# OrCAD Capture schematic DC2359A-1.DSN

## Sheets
1 PAGE2: size A
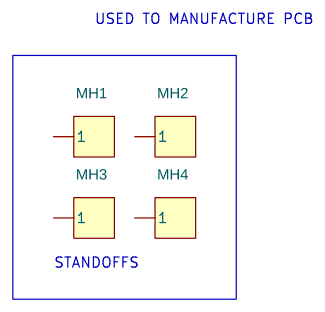
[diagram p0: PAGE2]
2 PAGE1: size Custom; title: MONOLITHIC SYNCHRONOUS BUCK REGULATOR; rev: 1; company: TM; note: WITH ULTRA-LOW QUIESCENT CURRENT
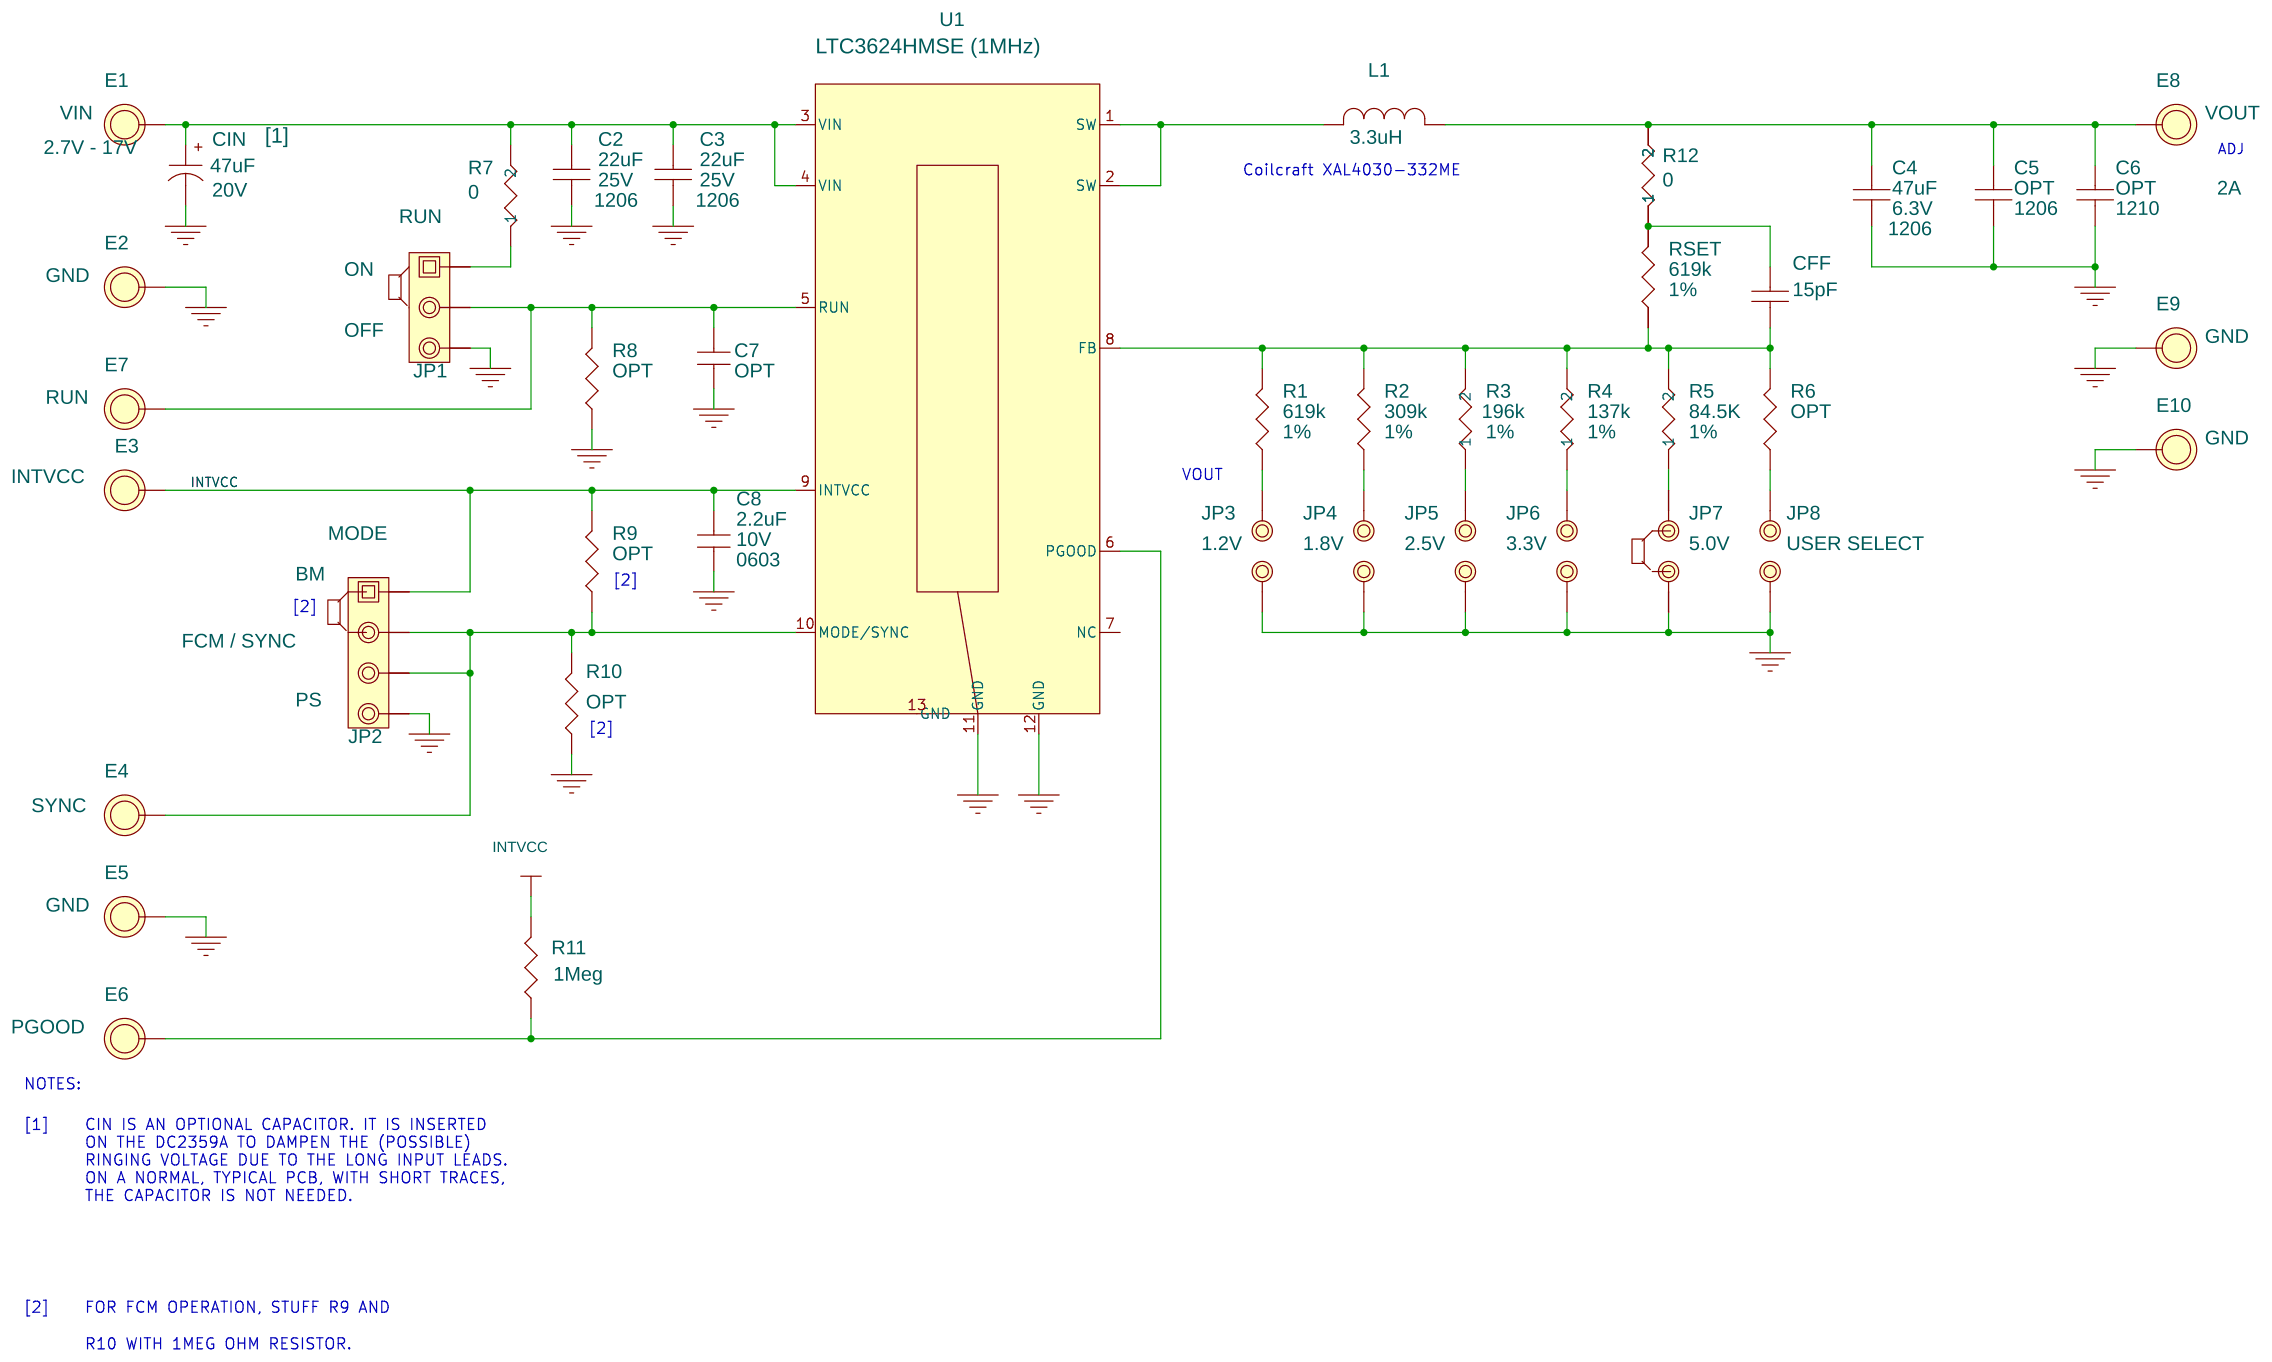
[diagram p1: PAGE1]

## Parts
sheet PAGE1
C2  22uF  [1206]
C3  22uF  [1206]
C4  47uF  [1206]
C5  OPT  [1206]
C6  OPT  [1210]
C7  OPT  [0402]
C8  2.2uF  [0603]
CFF  15pF  [0402]
CIN  47uF  [7343]
E1  2.7V - 17V  [TP\MMX\2501-2]
E2  2.7V - 17V  [TP\MMX\2501-2]
E3  3.6V  [TP\MMX\2501-2]
E4  3A  [TP\MMX\2501-2]
E5  2.7V - 17V  [TP\MMX\2501-2]
E6  3A  [TP\MMX\2501-2]
E7  2.7V - 17V  [TP\MMX\2501-2]
E8  2A  [TP\MMX\2501-2]
E9  2A  [TP\MMX\2501-2]
E10  2A  [TP\MMX\2501-2]
JP1  3 Pins 2mm Ctrs.  [SIP\3P\2MM]
JP2  3 Pins 2mm Ctrs.  [SIP\4P\2MM]
JP3  2 Pins 2mm Ctrs.  [SIP\2P\2MM]
JP4  2 Pins 2mm Ctrs.  [SIP\2P\2MM]
JP5  2 Pins 2mm Ctrs.  [SIP\2P\2MM]
JP6  2 Pins 2mm Ctrs.  [SIP\2P\2MM]
JP7  2 Pins 2mm Ctrs.  [SIP\2P\2MM]
JP8  2 Pins 2mm Ctrs.  [SIP\2P\2MM]
L1  3.3uH  [IND\CLCRF_XAL4020]
R1  619k  [R0402]
R2  309k  [R0402]
R3  196k  [R0402]
R4  137k  [R0402]
R5  84.5K  [R0402]
R6  OPT  [R0402]
R7  0  [R0402]
R8  OPT  [0402]
R9  OPT  [R0402]
R10  OPT  [0402]
R11  1Meg  [0402]
R12  0  [R0402]
RSET  619k  [R0402]
U1  LTC3624HMSE (1MHz)  [LT_MSE_12]
XJP1  2mm Ctrs.
XJP2  2mm Ctrs.
XJP3  2mm Ctrs.
sheet PAGE2
MH1  CON1  [KEYSTONE_8831]
MH2  CON1  [KEYSTONE_8831]
MH3  CON1  [KEYSTONE_8831]
MH4  CON1  [KEYSTONE_8831]

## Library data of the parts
C2 C3 = CAP_NP: CAP, 1206 22uF10% 25V X5R; FIELD1: 0805; Part Number: MURATA GRM31CR61E226KE15L; Tolerance: X5R; Voltage: 25V
C4 = CAP_NP: CAP, 1206 47uF 20% 6.3V X5R; FIELD1: 0805; Part Number: TAIYO YUDEN JMK316BJ476ML-T; Tolerance: X5R; Voltage: 6.3V
C5 = CAP_NP: CAP, 1206 22uF 20% 6.3V X5R OPTION; FIELD1: 0805; Part Number: TAIYO YUDEN EMK316BJ226ML-T OPTION; Tolerance: X5R; Voltage: 6.3V
C6 = CAP_NP_0: CAP, 1210 OPTION; Part Number: OPTION
C7 = CAP0603: CAP, 0402 OPTION; Part Number: OPTION
C8 = CAP0402: CAP, 0603 2.2uF 10% 10V X5R; 1ST PART FIELD: 10V; Part Number: AVX 0603ZDF225KAT2A
CFF = CAP_NP: CAP, 0402 15pF 1% 50V C0G; Case: 1206; Part Number: AVX 04025U150FAT2A; Tolerance: NPO; Voltage: 50V
CIN = CAP+7343: CAP, 47uF 20% 20V 33m Ohm; 1ST PART FIELD: 20V; 2ND PART FIELD: OPT; 4TH PART FIELD: [1]; Part Number: PANASONIC OSCON 20SVPA47M
E1 = E_4: TURRET; INPUT: VIN; Part Number: MILL-MAX 2501-2-00-80-00-00-07-0; STATUS: 1.6V, 1.8V, 2.0V OR 2.5V @ 15A
E2 E5 E9 E10 = E_4: TURRET; INPUT: GND; Part Number: MILL-MAX 2501-2-00-80-00-00-07-0; STATUS: 1.6V, 1.8V, 2.0V OR 2.5V @ 15A
E3 = E_4: TURRET; INPUT: INTVCC; Part Number: MILL-MAX 2501-2-00-80-00-00-07-0; STATUS: 1.6V, 1.8V, 2.0V OR 2.5V @ 15A
E4 = E_4: TURRET; INPUT: SYNC; Part Number: MILL-MAX 2501-2-00-80-00-00-07-0; STATUS: 1.6V, 1.8V, 2.0V OR 2.5V @ 15A
E6 = E_4: TURRET; INPUT: PGOOD; Part Number: MILL-MAX 2501-2-00-80-00-00-07-0; STATUS: 1.6V, 1.8V, 2.0V OR 2.5V @ 15A
E7 = E_4: TURRET; INPUT: RUN; Part Number: MILL-MAX 2501-2-00-80-00-00-07-0; STATUS: 1.6V, 1.8V, 2.0V OR 2.5V @ 15A
E8 = E_4: TURRET; INPUT: VOUT; Part Number: MILL-MAX 2501-2-00-80-00-00-07-0; STATUS: 1.6V, 1.8V, 2.0V OR 2.5V @ 15A
JP1 = Samtec_TMM-103-02-L-S: HEADER, 3PIN, 2mm; 11th Part Field: OFF; 12th Part Field: RUN; 9th Part Field: ON; Part Number: WURTH 620 003 111 21
JP2 = Samtec_TMM-103-02-L-S_0: HEADER, 4PIN, 2mm; 11th Part Field: FCM / SYNC; 12th Part Field: MODE; 4th Part Field: PS; 5th Part Field: ON1_CONTROL; 9th Part Field: BM; Part Number: SAMTEC TMM-104-02-L-S
JP3 = Samtec_TMM-102-02-L-S_4: HEADER, 2PIN, 2mm; 9th Part Field: 1.2V; Part Number: SAMTEC TMM 102-02-L-S
JP4 = Samtec_TMM-102-02-L-S_5: HEADER, 2PIN, 2mm; 9th Part Field: 1.8V; Part Number: SAMTEC TMM 102-02-L-S
JP5 = Samtec_TMM-102-02-L-S_3: HEADER, 2PIN, 2mm; 9th Part Field: 2.5V; Part Number: SAMTEC TMM 102-02-L-S
JP6 = Samtec_TMM-102-02-L-S_2: HEADER, 2PIN, 2mm; 9th Part Field: 3.3V; Part Number: SAMTEC TMM 102-02-L-S
JP7 = Samtec_TMM-102-02-L-S: HEADER, 2PIN, 2mm; 9th Part Field: 5.0V; Part Number: SAMTEC TMM 102-02-L-S
JP8 = Samtec_TMM-102-02-L-S_1: HEADER, 2PIN, 2mm; 9th Part Field: USER SELECT; Part Number: SAMTEC TMM 102-02-L-S
L1 = D53LC: IND, 3.3uH; Part Number: COILCRAFT XAL4030-332ME
R1 RSET = RESISTOR: RES, 0402 619K OHM 1% 1/16W; Part Number: VISHAY CRCW0402619KFKED; Tol: 1%
R2 = RESISTOR: RES, 0402 309k OHMS 1% 1/16W; Part Number: VISHAY CRCW0402309KFKED; Tolerance: 1%
R3 = R_1: RES, 0402 196K OHMS 1% 1/16W; 5%: 1%; Part Number: VISHAY CRCW0402196KFKEA; Tol: 1%
R4 = R: RES, 0402 137K OHMS 1% 1/16W; 5%: 1%; Part Number: VISHAY CRCW0402137KFKED; Tol: 1%
R5 = R_2: RES, 0402 84.5K OHMS 1% 1/16W; 5%: 1%; Part Number: VISHAY CRCW040284K5FKED
R6 = RESISTOR: RES, 0402 OPTION; Part Number: OPTION; Tolerance: 1%
R7 = R_4: RES, 0402 0 OHM JUMPER; 5%: 1%; Part Number: VISHAY CRCW04020000Z0ED
R8 = RESISTOR: RES, 0402 OPTION; Part Number: OPTION
R9 = RESISTOR: RES, 0402 OPTION; Part Number: OPTION; Tol: <Tol>
R10 = AAC-0402: RES, 0402 OPTION; 4TH PART FIELD: AAC,; Part Number: OPTION
R11 = AAC-0402: RES, 0402 1M OHMS 5% 1/16W; 4TH PART FIELD: AAC,; Part Number: VISHAY CRCW04021M00JNED
R12 = R_3: RES, 0402 0 OHM JUMPER; 5%: 1%; Part Number: VISHAY CRCW04020000Z0ED
U1 = LTC3624HMSE: IC, MONOLITHIC SYNCHRONOUS BUCK REGULATOR; Part Number: LINEAR TECH LTC3624HMSE #PBF
XJP1-XJP3 = Samtec_2SN-BK-G: SHUNT, 2mm; Part Number: SAMTEC 2SN-BK-G
MH1-MH4 = CON1: STANDOFF, SNAP ON; Part Number: KEYSTONE_8833

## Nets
GND: C2.2 C3.2 C4.2 C5.2 C6.2 C7.2 C8.2 CIN.2 E2.1(A) E5.1(A) E9.1(A) E10.1(A) JP1.3 JP2.4 JP3.1 JP4.1 JP5.1 JP6.1 JP7.1 JP8.1 R8.1 R10.1 U1.11(GND) U1.12(GND) U1.13(GND)
INTVCC: C8.1 E3.1(A) JP2.1 R9.2 R11.2 U1.9(INTVCC)
N16787415: JP3.2 R1.1
N16787417: JP4.2 R2.1
N16787419: JP5.2 R3.1
N16787421: JP6.2 R4.1
N16787423: JP8.2 R6.1
N16789696: C7.1 E7.1(A) JP1.2 R8.2 U1.5(RUN)
N16790574: JP1.1 R7.1
N16791168: C2.1 C3.1 CIN.1 E1.1(A) R7.2 U1.3(VIN) U1.4(VIN)
N16793542: E4.1(A) JP2.2 JP2.3 R9.1 R10.2 U1.10(MODE/SYNC)
N16798106: JP7.2 R5.1
N16800745: E6.1(A) R11.1 U1.6(PGOOD)
N16803973: CFF.2 R1.2 R2.2 R3.2 R4.2 R5.2 R6.2 RSET.1 U1.8(FB)
N16804749: L1.1 U1.1(SW) U1.2(SW)
N16804855: C4.1 C5.1 C6.1 E8.1(A) L1.2 R12.2
N16854814: CFF.1 R12.1 RSET.2

Not connected (* = marked no-connect by the designer): MH1 1; MH2 1; MH3 1; MH4 1; U1 7(NC)

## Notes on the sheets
sheet 1
- USED TO MANUFACTURE PCB
- STANDOFFS
sheet 2
- ADJ
- Coilcraft XAL4030-332ME
- VOUT
- [2]
- [2]
- [2]
- NOTES:
- [1]
- CIN IS AN OPTIONAL CAPACITOR. IT IS INSERTED
  ON THE DC2359A TO DAMPEN THE (POSSIBLE)
  RINGING VOLTAGE DUE TO THE LONG INPUT LEADS.
  ON A NORMAL, TYPICAL PCB, WITH SHORT TRACES,
  THE CAPACITOR IS NOT NEEDED.
- [2]
- FOR FCM OPERATION, STUFF R9 AND
- R10 WITH 1MEG OHM RESISTOR.
